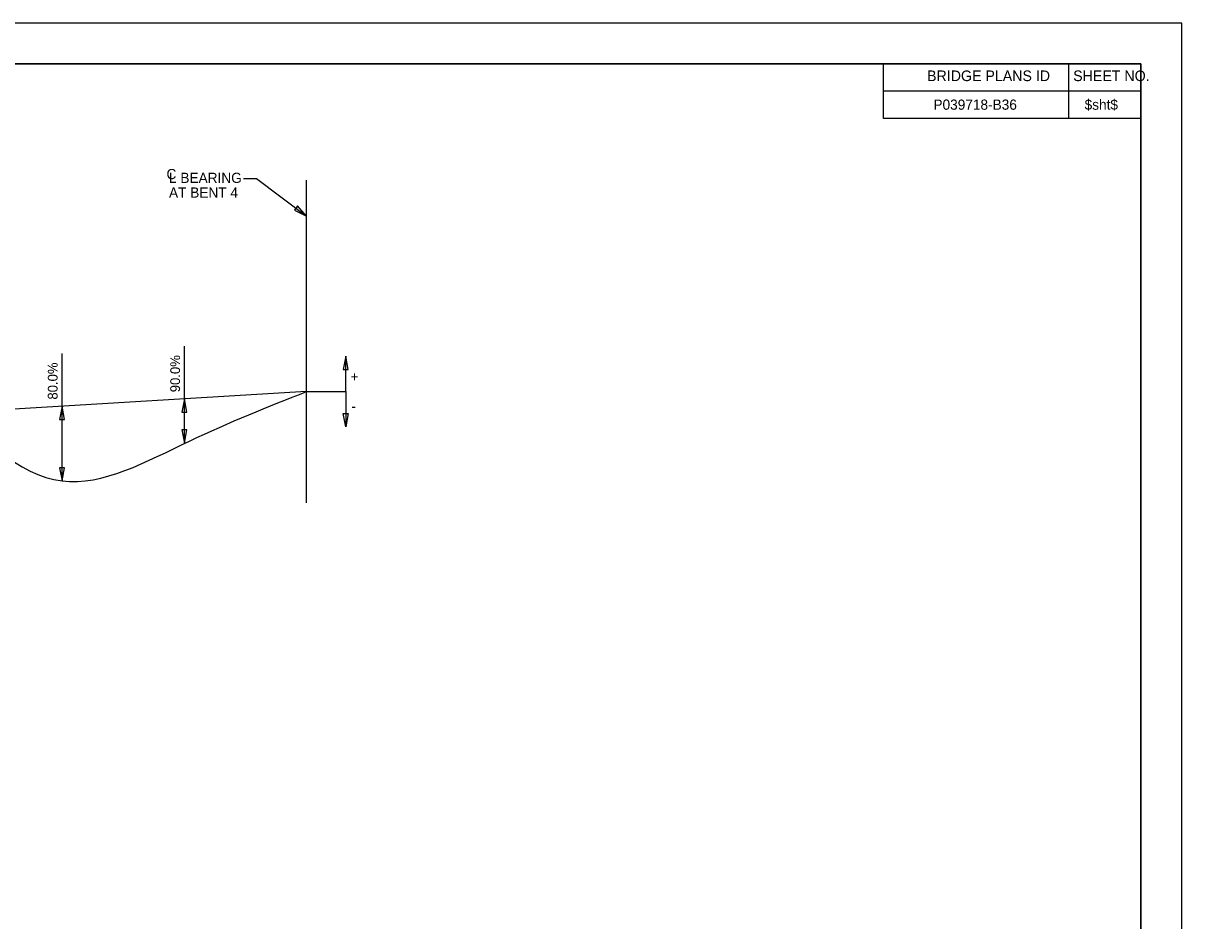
# Model space of a CAD drawing. Extents: x -125.5 to -89.4, y -5.1 to 16.9.
# Drawn here: x -103.73 to -89.53, y 5.93 to 16.93 of the extents above; entities that cross this region are included whole.
import ezdxf

# ---------------------------------------------------------------- set-up
doc = ezdxf.new("R2010")
doc.units = 0
for name, color, linetype in [('BR_AUTO DIMENSION', 7, 'Continuous'), ('BR_BORDER LINES', 7, 'Continuous'), ('BR_CENTER LINES', 7, 'Continuous'), ('BR_TABLE LINES', 7, 'Continuous'), ('BR_TEXT', 7, 'Continuous'), ('Level 31', 7, 'Continuous')]:
    doc.layers.add(name, color=color, linetype=linetype)

msp = doc.modelspace()

# ---------------------------------------------------------------- linework, layer by layer
at = {"layer": 'BR_AUTO DIMENSION'}
for p, q in [((-101.03, 15.029), (-100.87, 15.029)), ((-100.87, 15.029), (-100.257, 14.57)), ((-100.257, 12.42), (-99.777, 12.42))]:
    msp.add_line(p, q, dxfattribs=at)
for points in [[(-100.405, 14.644), (-100.257, 14.57), (-100.367, 14.694)], [(-99.746, 12.691), (-99.777, 12.854), (-99.809, 12.691)], [(-103.222, 12.078), (-103.253, 12.241), (-103.285, 12.078)], [(-101.722, 12.168), (-101.753, 12.331), (-101.785, 12.168)], [(-99.746, 12.15), (-99.777, 11.987), (-99.809, 12.15)], [(-101.785, 11.949), (-101.753, 11.786), (-101.722, 11.949)], [(-103.285, 11.486), (-103.253, 11.324), (-103.222, 11.486)]]:
    msp.add_lwpolyline(points, close=True, dxfattribs=at)
at = {"layer": 'BR_BORDER LINES'}
for p, q in [((-90.033, 16.434), (-123.699, 16.434)), ((-93.186, 15.767), (-93.186, 16.434)), ((-90.919, 15.767), (-90.919, 16.434)), ((-90.033, -4.566), (-90.033, 16.434)), ((-93.186, 16.104), (-90.033, 16.104)), ((-90.919, 16.104), (-90.033, 16.104)), ((-90.033, 15.767), (-93.186, 15.767))]:
    msp.add_line(p, q, dxfattribs=at)
at = {"layer": 'BR_CENTER LINES'}
msp.add_line((-100.257, 11.055), (-100.257, 15.009), dxfattribs=at)
at = {"layer": 'BR_TABLE LINES'}
for p, q in [((-101.753, 12.331), (-101.753, 12.975)), ((-101.753, 11.786), (-101.753, 12.975)), ((-103.253, 11.324), (-103.253, 12.885)), ((-99.777, 12.42), (-99.777, 12.854)), ((-100.257, 12.42), (-115.253, 11.521)), ((-99.777, 12.42), (-99.777, 11.987))]:
    msp.add_line(p, q, dxfattribs=at)
msp.add_lwpolyline([(-123.699, 16.434), (-90.033, 16.434), (-90.033, -4.566), (-123.699, -4.566)], close=True, dxfattribs=at)
msp.add_spline([(-115.253, 11.521), (-113.753, 12.621), (-112.253, 13.551), (-110.753, 14.181), (-109.253, 14.421), (-107.753, 14.211), (-106.253, 13.521), (-104.724, 12.313), (-103.253, 11.324), (-101.692, 11.812), (-100.257, 12.42)], degree=3, dxfattribs=at)
at = {"layer": 'Level 31'}
msp.add_lwpolyline([(-125.533, -5.066), (-89.533, -5.066), (-89.533, 16.934), (-125.533, 16.934)], close=True, dxfattribs=at)

# ---------------------------------------------------------------- texts
at = {"layer": 'BR_AUTO DIMENSION'}
for s, p in [('C', (-101.973, 15.022)), ('L BEARING', (-101.942, 14.976)), ('AT BENT 4', (-101.942, 14.796))]:
    msp.add_text(s, height=0.125, dxfattribs=at).set_placement(p)
at = {"layer": 'BR_TEXT'}
for s, height, p in [('BRIDGE PLANS ID', 0.13, (-92.654, 16.224)), ('SHEET NO.', 0.13, (-90.864, 16.224)), ('P039718-B36', 0.125, (-92.576, 15.873)), ('$sht$', 0.125, (-90.724, 15.873)), ('-', 0.12, (-99.706, 12.18))]:
    msp.add_text(s, height=height, dxfattribs=at).set_placement(p)
for s, rotation, p in [('90.0%', 90, (-101.807, 12.411)), ('80.0%', 90, (-103.307, 12.321)), ('+', 360, (-99.716, 12.541))]:
    msp.add_text(s, height=0.12, rotation=rotation, dxfattribs=at).set_placement(p)

doc.saveas('drawing.dxf')
